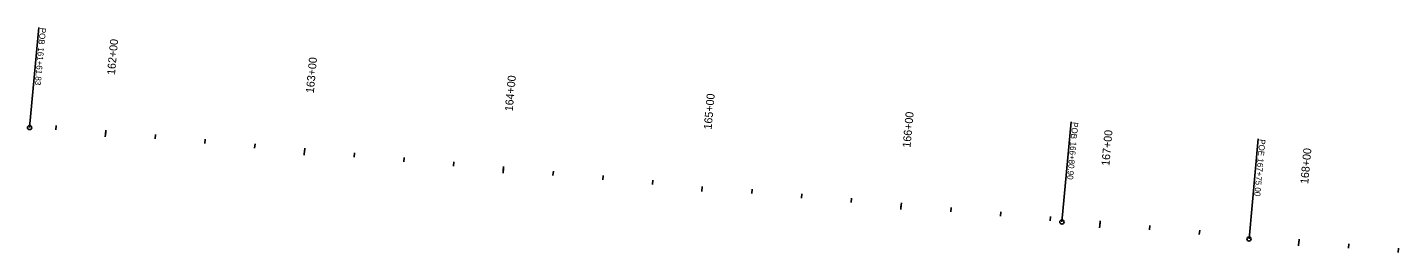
# Model space of a CAD drawing. Extents: x 20499876 to 20505320, y 7953544 to 7954108.
# Drawn here: x 20499876 to 20500563, y 7953995 to 7954108 of the extents above; entities that cross this region are included whole.
import ezdxf

# ---------------------------------------------------------------- set-up
doc = ezdxf.new("R2010")
doc.units = 0
for name, color, linetype in [('Draft_7', 7, 'Continuous'), ('PS_CONST', 7, 'Continuous'), ('Revetment', 7, 'Continuous')]:
    doc.layers.add(name, color=color, linetype=linetype)

msp = doc.modelspace()

# ---------------------------------------------------------------- linework, layer by layer
at = {"layer": 'Draft_7'}
for p, q in [((20499890.59, 7954056.75), (20499890.79, 7954058.93)), ((20499915.6, 7954055.7), (20499915.37, 7954053.26)), ((20499940.38, 7954052.2), (20499940.58, 7954054.37)), ((20499965.28, 7954049.92), (20499965.48, 7954052.09)), ((20499990.17, 7954047.64), (20499990.37, 7954049.82)), ((20500015.18, 7954046.58), (20500014.96, 7954044.14)), ((20500039.97, 7954043.09), (20500040.16, 7954045.26)), ((20500064.86, 7954040.81), (20500065.06, 7954042.98)), ((20500089.76, 7954038.53), (20500089.96, 7954040.7)), ((20500114.76, 7954037.47), (20500114.54, 7954035.03)), ((20500139.55, 7954033.97), (20500139.75, 7954036.15)), ((20500164.45, 7954031.69), (20500164.64, 7954033.87)), ((20500189.34, 7954029.42), (20500189.54, 7954031.59)), ((20500214.35, 7954028.36), (20500214.13, 7954025.92)), ((20500239.13, 7954024.86), (20500239.33, 7954027.03)), ((20500264.03, 7954022.58), (20500264.23, 7954024.76)), ((20500288.93, 7954020.3), (20500289.12, 7954022.48)), ((20500313.93, 7954019.24), (20500313.71, 7954016.81)), ((20500338.72, 7954015.75), (20500338.92, 7954017.92)), ((20500363.61, 7954013.47), (20500363.81, 7954015.64)), ((20500388.51, 7954011.19), (20500388.71, 7954013.36)), ((20500413.52, 7954010.13), (20500413.29, 7954007.69)), ((20500413.52, 7954010.13), (20500413.29, 7954007.69)), ((20500438.3, 7954006.63), (20500438.5, 7954008.81)), ((20500438.3, 7954006.63), (20500438.5, 7954008.81)), ((20500463.2, 7954004.36), (20500463.4, 7954006.53)), ((20500463.2, 7954004.36), (20500463.39, 7954006.53)), ((20500488.09, 7954002.08), (20500488.29, 7954004.25)), ((20500513.1, 7954001.02), (20500512.88, 7953998.58)), ((20500537.88, 7953997.52), (20500538.08, 7953999.7)), ((20500562.78, 7953995.24), (20500562.98, 7953997.42))]:
    msp.add_line(p, q, dxfattribs=at)
at = {"layer": 'PS_CONST'}
for p, q in [((20499915.49, 7954054.48), (20499915.68, 7954056.65)), ((20500015.07, 7954045.36), (20500015.27, 7954047.54)), ((20500114.65, 7954036.25), (20500114.85, 7954038.43)), ((20500214.35, 7954028.36), (20500214.13, 7954025.92)), ((20500313.82, 7954018.02), (20500314.02, 7954020.2)), ((20500413.4, 7954008.91), (20500413.6, 7954011.09)), ((20500413.4, 7954008.91), (20500413.6, 7954011.09)), ((20500512.99, 7953999.8), (20500513.19, 7954001.97))]:
    msp.add_line(p, q, dxfattribs=at)
at = {"layer": 'Revetment'}
for p, q in [((20499877.47, 7954057.95), (20499882.07, 7954108.14)), ((20499882.07, 7954108.14), (20499882.07, 7954108.14)), ((20500394.39, 7954010.65), (20500398.98, 7954060.84)), ((20500398.98, 7954060.84), (20500398.98, 7954060.84)), ((20500488.09, 7954002.08), (20500492.68, 7954052.27)), ((20500492.68, 7954052.27), (20500492.68, 7954052.27))]:
    msp.add_line(p, q, dxfattribs=at)
for centre in [(20499877.47, 7954057.95), (20500394.39, 7954010.65), (20500488.09, 7954002.08)]:
    msp.add_circle(centre, 1.07, dxfattribs=at)

# ---------------------------------------------------------------- texts
at = {"layer": 'Draft_7'}
for s, p in [('162+00', (20499920.21, 7954084.17)), ('163+00', (20500019.8, 7954075.06)), ('164+00', (20500119.38, 7954065.94)), ('165+00', (20500218.97, 7954056.83)), ('166+00', (20500318.55, 7954047.72)), ('167+00', (20500418.13, 7954038.6)), ('167+00', (20500418.13, 7954038.6)), ('168+00', (20500517.72, 7954029.49))]:
    msp.add_text(s, height=4.008, rotation=84.77145, dxfattribs=at).set_placement(p)
at = {"layer": 'PS_CONST'}
msp.add_text('165+00', height=4.008, rotation=84.77145, dxfattribs=at).set_placement((20500218.97, 7954056.83))
at = {"layer": 'Revetment'}
for s, p in [('POB ', (20499882.72, 7954108.08)), ('161+61.83', (20499881.82, 7954098.27)), ('POB ', (20500399.63, 7954060.78)), ('POE ', (20500493.34, 7954052.21)), ('166+80.90', (20500398.74, 7954050.97)), ('167+75.00', (20500492.46, 7954042.62))]:
    msp.add_text(s, height=3, rotation=264.77145, dxfattribs=at).set_placement(p)

doc.saveas('drawing.dxf')
